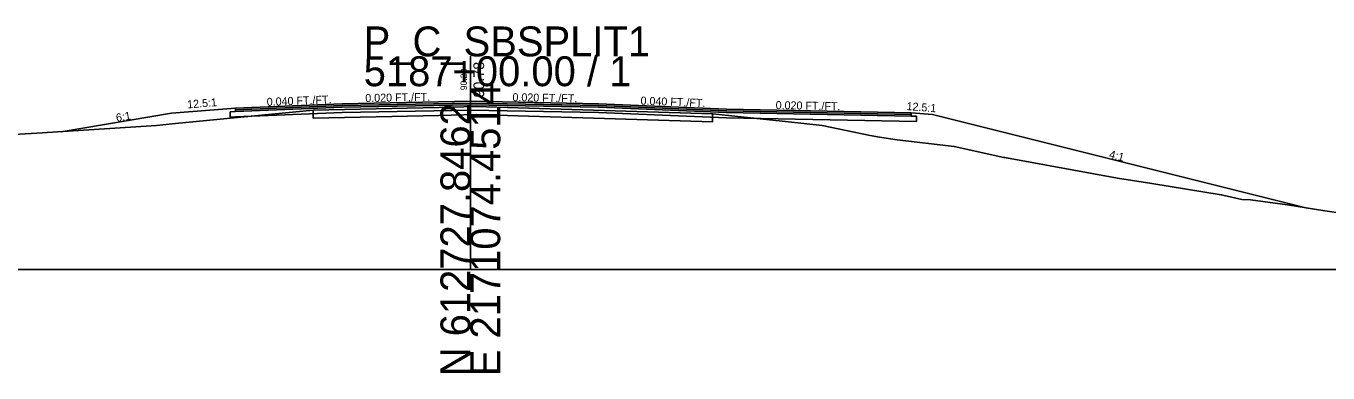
# Model space of a CAD drawing. Extents: x -26 to 1303, y -3010 to 12023.
# Drawn here: x 108.4 to 230.4, y 7990.3 to 8022.8 of the extents above; entities that cross this region are included whole.
import ezdxf

# ---------------------------------------------------------------- set-up
doc = ezdxf.new("R2010")
doc.units = 0
for name, color, linetype in [('RD_GPK_XS_Cell', 7, 'Continuous'), ('RD_XS_Base', 7, 'Continuous'), ('RD_XS_ExGround', 7, 'Continuous'), ('RD_XS_ExPaveRet', 7, 'Continuous'), ('RD_XS_Greenside', 7, 'Continuous'), ('RD_XS_Pave', 7, 'Continuous'), ('RD_XS_PaveOvlay_CP', 7, 'Continuous'), ('RD_XS_TieSlope', 7, 'Continuous'), ('RD_XS_TX_Elev_EX', 7, 'Continuous'), ('RD_XS_TX_Elev_PR', 7, 'Continuous'), ('RD_XS_TX_ShdSlope', 7, 'Continuous'), ('RD_XS_TX_Slope', 7, 'Continuous')]:
    doc.layers.add(name, color=color, linetype=linetype)

msp = doc.modelspace()

# ---------------------------------------------------------------- linework, layer by layer
at = {"layer": 'RD_GPK_XS_Cell'}
for p, q in [((150, 8000), (150, 8020)), ((0, 8000), (150, 8000)), ((150, 8000), (300, 8000))]:
    msp.add_line(p, q, dxfattribs=at)
at = {"layer": 'RD_XS_Base'}
for p, q in [((128, 8014.82), (127.5, 8014.8)), ((127.5, 8014.8), (127.5, 8014.8)), ((127.5, 8014.8), (127.5, 8014.3)), ((138, 8015.22), (128, 8014.82)), ((128, 8014.82), (128, 8014.82)), ((128, 8014.32), (138, 8014.72)), ((136, 8015.14), (136, 8015.14)), ((150, 8015.46), (138, 8015.22)), ((138, 8014.72), (150, 8014.96)), ((150, 8014.96), (150, 8015.62)), ((150, 8015.62), (150, 8015.62)), ((150, 8015.62), (150, 8015.62)), ((150, 8015.62), (150, 8015.46)), ((150, 8015.46), (150, 8015.46)), ((150, 8015.46), (162, 8015.22)), ((150, 8015.46), (150, 8015.46)), ((150, 8014.96), (150, 8015.46)), ((150, 8015.46), (150, 8015.46)), ((150, 8015.46), (150, 8015.46)), ((162, 8014.72), (150, 8014.96)), ((150, 8014.96), (150, 8014.96)), ((150, 8014.96), (150, 8014.96)), ((162, 8015.22), (162, 8015.22)), ((162, 8015.22), (174, 8014.74)), ((174, 8014.24), (162, 8014.72)), ((162, 8014.72), (162, 8014.72)), ((174, 8014.74), (174, 8014.74)), ((174, 8014.74), (191.32, 8014.39)), ((127.5, 8014.3), (128, 8014.32)), ((128, 8014.32), (128, 8014.32)), ((136, 8014.64), (136, 8014.64)), ((191.82, 8013.88), (174, 8014.24)), ((174, 8014.24), (174, 8014.24)), ((191.32, 8014.39), (191.32, 8014.39)), ((191.32, 8014.39), (191.82, 8014.38)), ((191.82, 8014.38), (191.82, 8014.38)), ((191.82, 8014.38), (191.82, 8013.88))]:
    msp.add_line(p, q, dxfattribs=at)
at = {"layer": 'RD_XS_ExGround'}
msp.add_lwpolyline([(104.47, 8012.51), (109.36, 8012.78), (120.59, 8013.51), (122.37, 8013.69), (135.27, 8014.96), (147.05, 8015.2), (150.55, 8015.29), (154.46, 8015.16), (172.71, 8014.62), (179.55, 8013.88), (182.98, 8013.5), (187.48, 8012.58), (188.34, 8012.42), (189.99, 8012.17), (195.34, 8011.55), (199.99, 8010.52), (200.07, 8010.5), (200.1, 8010.5), (200.24, 8010.47), (210.66, 8008.56), (213.87, 8008.09), (220.38, 8007.02), (222.32, 8006.57), (223.13, 8006.54), (226.58, 8006.07), (230.1, 8005.5), (231.82, 8005.26)], dxfattribs=at)
at = {"layer": 'RD_XS_ExPaveRet'}
for points in [[(172.71, 8014.62), (172.71, 8014.62), (172.71, 8013.87), (172.71, 8013.87), (154.46, 8014.41), (154.46, 8014.41), (150.55, 8014.54), (150.55, 8014.54), (150.55, 8014.54), (147.05, 8014.45), (147.05, 8014.45), (135.27, 8014.21), (135.27, 8014.96), (135.27, 8014.96), (147.05, 8015.2), (147.05, 8015.2), (150.55, 8015.29), (150.55, 8015.29), (150.55, 8015.29), (154.46, 8015.16), (154.46, 8015.16), (172.71, 8014.62), (172.71, 8014.62)], [(172.71, 8014.62), (154.46, 8015.16), (150.55, 8015.29), (147.05, 8015.2), (135.27, 8014.96), (135.27, 8014.21), (147.05, 8014.45), (150.55, 8014.54), (154.46, 8014.41), (172.71, 8013.87), (172.71, 8013.87), (172.71, 8014.62), (172.71, 8014.62)]]:
    msp.add_lwpolyline(points, dxfattribs=at)
at = {"layer": 'RD_XS_Greenside'}
for p, q in [((122, 8014.66), (111.64, 8012.93)), ((193.32, 8014.55), (228.44, 8005.77))]:
    msp.add_line(p, q, dxfattribs=at)
at = {"layer": 'RD_XS_Pave'}
for p, q in [((138, 8015.54), (128, 8015.14)), ((138, 8015.38), (128, 8014.98)), ((128, 8014.98), (138, 8015.38)), ((128, 8014.82), (138, 8015.22)), ((128, 8015.14), (128, 8015.14)), ((128, 8015.14), (128, 8014.98)), ((128, 8014.98), (128, 8014.98)), ((128, 8014.98), (128, 8014.82)), ((136, 8015.46), (136, 8015.46)), ((136, 8015.3), (136, 8015.3)), ((136, 8015.3), (136, 8015.3)), ((136, 8015.14), (136, 8015.14)), ((150, 8015.78), (138, 8015.54)), ((150, 8015.62), (138, 8015.38)), ((138, 8015.38), (150, 8015.62)), ((138, 8015.22), (150, 8015.46)), ((162, 8015.54), (150, 8015.78)), ((150, 8015.78), (150, 8015.78)), ((150, 8015.78), (150, 8015.78)), ((150, 8015.46), (150, 8015.62)), ((150, 8015.62), (150, 8015.62)), ((150, 8015.62), (150, 8015.62)), ((150, 8015.62), (150, 8015.62)), ((150, 8015.62), (150, 8015.62)), ((150, 8015.62), (162, 8015.38)), ((162, 8015.38), (150, 8015.62)), ((150, 8015.62), (150, 8015.62)), ((150, 8015.62), (150, 8015.62)), ((150, 8015.62), (150, 8015.62)), ((150, 8015.62), (150, 8015.46)), ((150, 8015.46), (150, 8015.46)), ((150, 8015.46), (150, 8015.46)), ((150, 8015.46), (150, 8015.46)), ((150, 8015.46), (162, 8015.22)), ((174, 8015.06), (162, 8015.54)), ((162, 8015.54), (162, 8015.54)), ((162, 8015.38), (162, 8015.38)), ((162, 8015.38), (174, 8014.9)), ((174, 8014.9), (162, 8015.38)), ((162, 8015.38), (162, 8015.38)), ((162, 8015.22), (162, 8015.22)), ((162, 8015.22), (174, 8014.74)), ((191.32, 8014.71), (174, 8015.06)), ((174, 8015.06), (174, 8015.06)), ((174, 8014.9), (174, 8014.9)), ((174, 8014.9), (191.32, 8014.55)), ((191.32, 8014.55), (174, 8014.9)), ((174, 8014.9), (174, 8014.9)), ((174, 8014.74), (191.32, 8014.39)), ((174, 8014.74), (174, 8014.74)), ((191.32, 8014.55), (191.32, 8014.71)), ((191.32, 8014.71), (191.32, 8014.71)), ((191.32, 8014.39), (191.32, 8014.55)), ((191.32, 8014.55), (191.32, 8014.55))]:
    msp.add_line(p, q, dxfattribs=at)
at = {"layer": 'RD_XS_PaveOvlay_CP'}
for p, q in [((138, 8015.54), (128, 8015.14)), ((136, 8015.46), (136, 8015.46)), ((150, 8015.78), (138, 8015.54)), ((162, 8015.54), (150, 8015.78)), ((150, 8015.78), (150, 8015.78)), ((150, 8015.78), (150, 8015.78)), ((174, 8015.06), (162, 8015.54)), ((162, 8015.54), (162, 8015.54)), ((191.32, 8014.71), (174, 8015.06)), ((174, 8015.06), (174, 8015.06))]:
    msp.add_line(p, q, dxfattribs=at)
at = {"layer": 'RD_XS_TieSlope'}
for p, q in [((128, 8015.14), (122, 8014.66)), ((191.32, 8014.71), (193.32, 8014.55))]:
    msp.add_line(p, q, dxfattribs=at)

# ---------------------------------------------------------------- texts
at = {"layer": 'RD_GPK_XS_Cell'}
for s, p in [('P_C_SBSPLIT1', (140, 8020)), ('5187+00.00 / 1', (140, 8017.2))]:
    msp.add_text(s, height=2.8, dxfattribs=at).set_placement(p)
for s, p in [('E 2171074.4514', (152.8, 7990)), ('N 612727.8462', (150, 7990))]:
    msp.add_text(s, height=2.8, rotation=90, dxfattribs=at).set_placement(p)
at = {"layer": 'RD_XS_TX_Elev_EX'}
msp.add_text('90.28', height=0.6, rotation=90, dxfattribs=at).set_placement((149.68, 8016.82))
at = {"layer": 'RD_XS_TX_Elev_PR'}
msp.add_text('90.78', height=1, rotation=90, dxfattribs=at).set_placement((151.29, 8016.14))
at = {"layer": 'RD_XS_TX_ShdSlope'}
for rotation, p in [(4.5739, (123.49, 8015.11)), (355.4261, (190.86, 8014.97))]:
    msp.add_text('12.5:1', height=0.75, rotation=rotation, dxfattribs=at).set_placement(p)
at = {"layer": 'RD_XS_TX_Slope'}
for s, rotation, p in [('0.040 FT./FT.', 2.2906, (130.93, 8015.35)), ('0.020 FT./FT.', 1.1458, (140.16, 8015.71)), ('0.020 FT./FT.', 358.8542, (153.94, 8015.8)), ('0.040 FT./FT.', 357.7094, (165.94, 8015.48)), ('6:1', 9.4623, (116.85, 8013.86)), ('0.020 FT./FT.', 358.8542, (178.61, 8015.06)), ('4:1', 345.9638, (209.82, 8010.48))]:
    msp.add_text(s, height=0.75, rotation=rotation, dxfattribs=at).set_placement(p)

doc.saveas('drawing.dxf')
